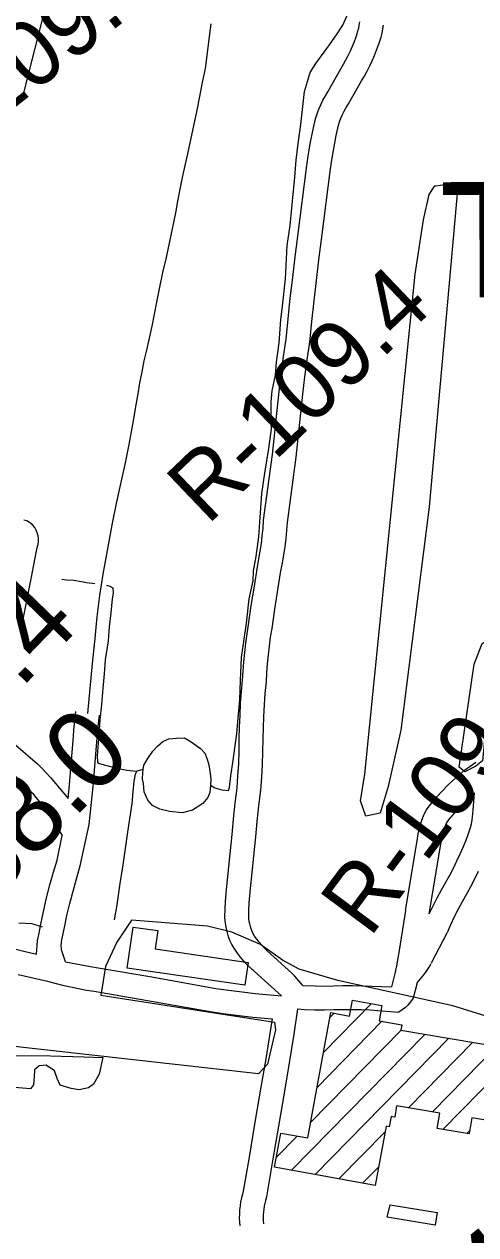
# Model space of a CAD drawing. Extents: x 3625074 to 3663148, y 511451 to 537151.
# Drawn here: x 3636401 to 3636969, y 521312 to 522833 of the extents above; entities that cross this region are included whole.
import ezdxf

# ---------------------------------------------------------------- set-up
doc = ezdxf.new("R2010")
doc.units = 0
for name, color, linetype in [('V-BLDG-OTLN', 7, 'Continuous'), ('V-RIVR-RANG-IDEN', 7, 'Continuous'), ('V-ROAD-CNTR', 7, 'Continuous'), ('V-SITE-OTLN', 7, 'Continuous'), ('V-SITE-VEGE', 7, 'Continuous'), ('V-SURV-IDEN', 7, 'Continuous'), ('V-TOPO-GNAM-IDEN', 7, 'Continuous'), ('V-TOPO-SHOR', 7, 'Continuous')]:
    doc.layers.add(name, color=color, linetype=linetype)

msp = doc.modelspace()

# ---------------------------------------------------------------- linework, layer by layer
at = {"layer": 'V-BLDG-OTLN'}
for p, q in [((3636777.2, 521541.2), (3636837.4, 521602.6)), ((3636769.2, 521497.4), (3636850.7, 521580.5)), ((3636785.2, 521585.1), (3636790.6, 521590.6)), ((3636737.3, 521393.4), (3636904.7, 521564.1)), ((3636761.2, 521453.5), (3636874.8, 521569.3)), ((3636767, 521388), (3636934.7, 521559.1)), ((3636884.2, 521471.8), (3636964.8, 521554)), ((3636914.2, 521466.7), (3636994.9, 521549)), ((3636927.5, 521444.6), (3636998, 521516.5)), ((3636796.8, 521382.6), (3636854.7, 521441.7)), ((3636957.6, 521439.6), (3636960.9, 521443)), ((3636718.2, 521409.6), (3636744.4, 521436.3)), ((3636826.5, 521377.2), (3636846.7, 521397.8))]:
    msp.add_line(p, q, dxfattribs=at)
for points in [[(3636538.1, 521698.9), (3636569, 521694.7), (3636565.6, 521671.7), (3636682.8, 521654.5), (3636678.6, 521625.7), (3636530.6, 521647.4)], [(3636857.3, 521334.4), (3636861.3, 521350.1), (3636920.3, 521340.1), (3636917.7, 521324.3)]]:
    msp.add_lwpolyline(points, close=True, dxfattribs=at)
msp.add_lwpolyline([(3636983.9, 521455.8), (3636963.7, 521459.2), (3636960.3, 521439.1), (3636920.2, 521445.8), (3636923.5, 521465.2), (3636869.2, 521474.3), (3636866.8, 521460.1), (3636862.3, 521461), (3636859.9, 521448), (3636856, 521448.8), (3636842.4, 521374.3), (3636715.9, 521397.3), (3636723.7, 521440.1), (3636757.7, 521433.9), (3636786.4, 521591.4), (3636810.1, 521587.1), (3636813.7, 521606.9), (3636850.7, 521600.2), (3636847.2, 521581.1), (3636875.9, 521576.2), (3636874.7, 521569.2), (3636998.5, 521548.4)], dxfattribs=at)
at = {"layer": 'V-ROAD-CNTR'}
msp.add_line((3636913.3, 521653.8), (3636932.7, 521691.6), dxfattribs=at)
for points in [[(3636398, 522737.1), (3636414.4, 522801.4), (3636427.4, 522852.1)], [(3636481, 521967.4), (3636484, 521998.8), (3636487.1, 522030.2), (3636490.5, 522061.6), (3636491.6, 522075.2), (3636492.9, 522088.7), (3636494.4, 522102.2), (3636496.1, 522115.6), (3636498.1, 522129), (3636500.3, 522142.4), (3636512.1, 522206.2), (3636517.2, 522230.9), (3636522.5, 522255.6), (3636528.1, 522280.2), (3636533.1, 522305.2), (3636537.7, 522330.2), (3636542, 522355.2), (3636544.2, 522369), (3636546.6, 522382.8), (3636549.3, 522396.5), (3636552.1, 522410.2), (3636555.2, 522423.8), (3636558.7, 522438.8), (3636562, 522453.8), (3636565, 522468.9), (3636567.7, 522484), (3636571.5, 522502.7), (3636575.5, 522521.4), (3636579.8, 522540), (3636591.6, 522596.1), (3636594.3, 522611), (3636597.1, 522626), (3636600.1, 522640.8), (3636603.4, 522655.7), (3636606.8, 522670.5), (3636618.5, 522725), (3636621.7, 522742.5), (3636625.1, 522760), (3636628.8, 522777.4), (3636635.5, 522827.4), (3636636.1, 522833.5)], [(3636724.4, 521612.4), (3636686, 521647.1), (3636681.5, 521651.4), (3636677.2, 521656), (3636673.2, 521660.9), (3636669.3, 521665.9), (3636665.7, 521671.1), (3636662, 521677), (3636659.7, 521682.1), (3636658, 521686.8), (3636656.5, 521691.6), (3636655.3, 521696.5), (3636654.4, 521701.4), (3636653.7, 521706.4), (3636653.4, 521711.6), (3636653.6, 521721.7), (3636654, 521731.4), (3636654.8, 521741), (3636655.8, 521750.4), (3636662.5, 521815.1), (3636664.2, 521834.6), (3636666.3, 521854.4), (3636668.7, 521873.7), (3636669.8, 521888.9), (3636670.7, 521904.3), (3636671.2, 521919.8), (3636671.5, 521935.4), (3636671.8, 521950.2), (3636672.4, 521965), (3636673.2, 521979.9), (3636674.3, 521994.7), (3636675.6, 522009.1), (3636676.3, 522020.4), (3636677.2, 522032.1), (3636678.4, 522043.8), (3636679.7, 522055.5), (3636681.2, 522067.1), (3636682.9, 522078.6), (3636686.6, 522102.8), (3636690.4, 522127.1), (3636694.3, 522151.6), (3636696.2, 522161.5), (3636697.8, 522171), (3636699.2, 522180.6), (3636700.4, 522190.2), (3636701.3, 522199.8), (3636702, 522210.1), (3636713.1, 522292.8), (3636721.6, 522371.8), (3636724.2, 522393.9), (3636727.1, 522415.9), (3636730.3, 522437.4), (3636732.8, 522463), (3636735.6, 522489), (3636738.6, 522514.9), (3636741.8, 522540.9), (3636745.2, 522566.7), (3636756.4, 522655.7), (3636758.6, 522670.3), (3636761.1, 522684.8), (3636763.9, 522699.2), (3636767.2, 522714.2), (3636769.3, 522720.6), (3636771.5, 522726.4), (3636774, 522732.1), (3636776.7, 522737.7), (3636779.7, 522743.2), (3636782.6, 522748.1), (3636799.3, 522777.2), (3636802.6, 522782.9), (3636805.6, 522788.4), (3636808.5, 522794), (3636811.2, 522799.7), (3636813.7, 522805.5), (3636816.1, 522811.3), (3636818.3, 522817.3), (3636819.6, 522821.2), (3636820.7, 522824.8), (3636821.6, 522828.4), (3636822.3, 522832.1), (3636822.9, 522836.2)], [(3636751.5, 521625.6), (3636741.4, 521637), (3636737.4, 521641), (3636706.6, 521668.9), (3636703, 521672.4), (3636699.7, 521676), (3636696.5, 521679.7), (3636693.6, 521683.5), (3636690.8, 521687.6), (3636688.6, 521691.1), (3636687.5, 521693.5), (3636686.4, 521696.6), (3636685.4, 521699.7), (3636684.6, 521702.8), (3636684, 521706), (3636683.6, 521709.3), (3636683.4, 521712.3), (3636683.6, 521720.7), (3636684, 521729.5), (3636684.7, 521738.2), (3636685.7, 521747.2), (3636692.4, 521812.2), (3636694.1, 521831.7), (3636696.2, 521851), (3636698.6, 521870.7), (3636699.8, 521887), (3636700.7, 521903), (3636701.2, 521919), (3636701.5, 521934.8), (3636701.8, 521949.3), (3636702.4, 521963.6), (3636703.2, 521977.9), (3636704.2, 521992.2), (3636705.6, 522006.8), (3636706.2, 522018.4), (3636707.1, 522029.5), (3636708.2, 522040.7), (3636709.5, 522051.8), (3636710.9, 522062.9), (3636712.6, 522074.1), (3636716.3, 522098.3), (3636720, 522122.4), (3636723.9, 522146.3), (3636725.8, 522156.2), (3636727.5, 522166.4), (3636729, 522176.7), (3636730.2, 522187), (3636731.2, 522197.3), (3636731.9, 522207), (3636742.8, 522289.2), (3636751.4, 522368.5), (3636754, 522390.2), (3636756.8, 522411.7), (3636760, 522433.7), (3636762.6, 522459.9), (3636765.4, 522485.6), (3636768.4, 522511.4), (3636771.6, 522537), (3636775, 522562.8), (3636786.1, 522651.6), (3636788.3, 522665.5), (3636790.7, 522679.3), (3636793.3, 522693.2), (3636796.2, 522706.3), (3636797.6, 522710.4), (3636799.3, 522715.1), (3636801.3, 522719.6), (3636803.4, 522724), (3636805.8, 522728.4), (3636808.6, 522733), (3636825.2, 522762.2), (3636828.7, 522768.1), (3636832.1, 522774.4), (3636835.4, 522780.8), (3636838.5, 522787.3), (3636841.4, 522793.8), (3636844.1, 522800.5), (3636846.5, 522807.1), (3636848.2, 522811.8), (3636849.7, 522816.9), (3636851, 522822.1), (3636851.9, 522827.3), (3636852.6, 522832.2)], [(3636400.2, 522087.9), (3636410.4, 522138.4), (3636412.7, 522151.8), (3636415.2, 522164.7), (3636418, 522177.4), (3636418.6, 522179.6), (3636419.1, 522183.3), (3636419, 522186.9), (3636418.6, 522190.6), (3636417.6, 522194.1), (3636416.2, 522197.5), (3636414.3, 522200.7), (3636411.5, 522204.4), (3636407.8, 522207.2), (3636404.3, 522209.1), (3636400.6, 522210.3)], [(3636452.9, 521655.1), (3636448.5, 521668.9), (3636448.1, 521670.8), (3636447.8, 521672.6), (3636447.6, 521674.5), (3636447.6, 521676.4), (3636447.8, 521678.4), (3636448, 521680.2), (3636448.6, 521682.9), (3636451.7, 521698.4), (3636454.9, 521713.5), (3636458.3, 521728.5), (3636462.5, 521743.9), (3636466.8, 521759.4), (3636471.6, 521775.6), (3636478.5, 521808.5), (3636482.6, 521827.8), (3636484.6, 521843.8), (3636486.3, 521859.4), (3636487.8, 521874.9), (3636493, 521936.5), (3636493.4, 521944), (3636494, 521951), (3636494.8, 521958), (3636495.9, 521965.2)], [(3636456.2, 521860.2), (3636457.9, 521877.6), (3636463.1, 521938.6), (3636463.5, 521946.1), (3636464.2, 521954), (3636465.1, 521961.9), (3636466.2, 521969.6)], [(3636367.2, 521944), (3636382.8, 521933.1), (3636390.7, 521927.3), (3636417.7, 521904), (3636423.5, 521898.3), (3636428.9, 521892.5), (3636434.2, 521886.6), (3636456.2, 521860.2)], [(3636345.3, 521922.7), (3636365.3, 521908.7), (3636371.9, 521903.8), (3636397.3, 521882), (3636402, 521877.3), (3636406.8, 521872.2), (3636411.4, 521867), (3636415.9, 521861.7), (3636420.3, 521856.1), (3636425.4, 521849.3), (3636430.4, 521842.5), (3636435.1, 521835.6), (3636449, 521814)], [(3636880.5, 521719.7), (3636894.7, 521804.7), (3636895.4, 521810), (3636896.4, 521815.9), (3636897.7, 521821.7), (3636899.3, 521827.4), (3636901.1, 521833.1), (3636903.2, 521838.6), (3636906.2, 521845.6), (3636913.4, 521854.8), (3636919.9, 521862.4), (3636926.6, 521869.8), (3636933.2, 521876.6), (3636939.9, 521883.1), (3636946.9, 521889.5), (3636954.4, 521896), (3636968.8, 521906.2)], [(3636910.2, 521715.3), (3636920.4, 521735.5), (3636925.8, 521745.6), (3636931.3, 521755.4), (3636936.1, 521764.2), (3636940.7, 521773), (3636945, 521781.9), (3636949.2, 521790.9), (3636953.2, 521799.9), (3636957, 521809.2), (3636958.9, 521814.1), (3636960.6, 521818.9), (3636962, 521823.8), (3636963.3, 521828.7), (3636964.2, 521833.2), (3636965.4, 521845.6), (3636967.1, 521867.7)], [(3636910.2, 521715.3), (3636924.4, 521800.4), (3636925.1, 521805.5), (3636925.8, 521810), (3636926.8, 521814.5), (3636928, 521818.9), (3636929.4, 521823.2), (3636931, 521827.5), (3636932.2, 521830.1), (3636936.6, 521835.8), (3636942.4, 521842.6), (3636948.5, 521849.2), (3636954.4, 521855.4), (3636967.1, 521867.7)], [(3636416.7, 521664.7), (3636417.9, 521681.6), (3636418.5, 521685.8), (3636419.3, 521689.1), (3636422.3, 521704.4), (3636425.6, 521720), (3636429.2, 521735.7), (3636433.5, 521751.8), (3636438, 521767.7), (3636442.5, 521782.9), (3636449, 521814)], [(3636120.5, 521776), (3636182, 521745.2), (3636243.7, 521713.8), (3636254.7, 521708.9), (3636266, 521704.2), (3636277.1, 521699.9), (3636288, 521696.7), (3636299.3, 521693.5), (3636310.7, 521690.5), (3636322.2, 521687.7), (3636334, 521685.1), (3636382.4, 521673.1), (3636400.6, 521668.6), (3636416.7, 521664.7)], [(3636933, 521692.2), (3636937.5, 521702.2), (3636942.1, 521712), (3636947, 521721.6), (3636952.1, 521731.2), (3636957.5, 521740.8), (3636962.6, 521750), (3636967.5, 521759.4), (3636972.1, 521768.9)], [(3636880.5, 521719.6), (3636872.4, 521669.4), (3636870.8, 521659.7), (3636869, 521650.1), (3636866.9, 521640.7), (3636862.9, 521623.8)], [(3636452.9, 521655.1), (3636484.4, 521649.4), (3636494.1, 521647.8), (3636561.5, 521636.2), (3636642, 521621.8), (3636658.4, 521619.5), (3636674.9, 521617.4), (3636691.4, 521615.6), (3636724.4, 521612.4)], [(3636393.5, 521639.4), (3636412, 521635), (3636430.2, 521630.9), (3636439.6, 521628.4), (3636449.4, 521625.9), (3636459.3, 521623.7), (3636469.3, 521621.6), (3636479.3, 521619.8), (3636489.1, 521618.2), (3636556.3, 521606.6), (3636637.3, 521592.2), (3636654.3, 521589.8), (3636671.3, 521587.6), (3636688.3, 521585.7), (3636712.7, 521583.4)], [(3636895.1, 521629), (3636903.4, 521638.9), (3636906.9, 521643.5), (3636910.1, 521648.3), (3636912.8, 521652.9)], [(3636751.5, 521625.6), (3636766.9, 521625), (3636778.4, 521624.8), (3636789.8, 521625.2), (3636801.7, 521625.3), (3636813.6, 521625.3), (3636825.4, 521625.1), (3636862.9, 521623.8)], [(3636895.1, 521629), (3636890, 521609.5)], [(3636890, 521609.5), (3636885.5, 521603.2), (3636883, 521600.4), (3636880.3, 521597.9), (3636872.2, 521592.1)], [(3636744.8, 521596.1), (3636740, 521564.2), (3636734.3, 521528.4), (3636728.3, 521492.7), (3636720.8, 521448.8), (3636713.3, 521405), (3636705.8, 521360.1), (3636704.4, 521355.4), (3636703.5, 521351.8), (3636702.7, 521348.2), (3636702.2, 521344.6), (3636701.8, 521341), (3636701.6, 521337.3), (3636701.5, 521333.7), (3636701.7, 521330), (3636702, 521326)], [(3636744.8, 521596.1), (3636753.6, 521595.5), (3636766, 521595), (3636778.7, 521594.8), (3636790.5, 521595.2), (3636801.9, 521595.3), (3636813.2, 521595.3), (3636824.6, 521595.1), (3636835.9, 521594.7), (3636845.8, 521594.1), (3636872.2, 521592.1)], [(3636712.7, 521583.4), (3636704.7, 521533.3), (3636698.7, 521497.7), (3636691.2, 521453.8), (3636683.7, 521409.9), (3636676.5, 521367), (3636675.5, 521363.4), (3636674.2, 521358.5), (3636673.2, 521353.5), (3636672.4, 521348.5), (3636671.9, 521343.5), (3636671.6, 521338.4), (3636671.5, 521333.3), (3636671.7, 521328.3), (3636672.1, 521323.5)]]:
    msp.add_lwpolyline(points, dxfattribs=at)
at = {"layer": 'V-SITE-OTLN'}
msp.add_lwpolyline([(3637141, 521537.4), (3636939.8, 521600.1), (3636795.3, 521631.8), (3636746.8, 521646.1), (3636726, 521657.4), (3636698.3, 521677), (3636662.3, 521692.6), (3636631.7, 521699.8), (3636535.8, 521707.5), (3636517.5, 521679.8), (3636503.3, 521649.3), (3636497.5, 521613.2), (3636715.7, 521579.5), (3636717, 521569.8), (3636706.9, 521526.7), (3636695.7, 521514.3), (3636377.4, 521550.1)], dxfattribs=at)
at = {"layer": 'V-SITE-VEGE'}
for points in [[(3636946.5, 522634.3), (3636910, 522227), (3636874.5, 521946.2), (3636858.6, 521875.4), (3636848.6, 521842.1), (3636830.5, 521838.1), (3636823.7, 521857.6), (3636829.5, 521890.9), (3636892.7, 522519.2), (3636903, 522587.3), (3636910.2, 522619.3), (3636917.2, 522630.3), (3636918.6, 522630.3)], [(3636947.8, 521899.8), (3636966.9, 522029), (3636976.8, 522055.3), (3636986.6, 522060.8), (3636990.7, 522051.1), (3636990.7, 522045.5), (3636977.1, 521907.9), (3636968.7, 521901), (3636954.8, 521894.1)]]:
    msp.add_lwpolyline(points, close=True, dxfattribs=at)
msp.add_lwpolyline([(3636389.8, 521537.6), (3636434.1, 521537.2), (3636476.1, 521535.8), (3636499.8, 521534.8), (3636495.5, 521514.2), (3636488.1, 521501.3), (3636482, 521496.8), (3636470.1, 521494.2), (3636460.2, 521496.2), (3636446.5, 521500.1), (3636442.7, 521508.5), (3636439.3, 521518.1), (3636428.7, 521525.4), (3636419.9, 521524.4), (3636414.1, 521519.4), (3636414.1, 521517.5), (3636412.8, 521500.7), (3636409, 521495.8), (3636383.8, 521497.9)], dxfattribs=at)
at = {"layer": 'V-TOPO-SHOR'}
for points in [[(3636635.1, 521877.3), (3636640.8, 521874), (3636649.6, 521871.2), (3636657.9, 521870.3), (3636659.2, 521874.3), (3636660.9, 521888.8), (3636663.6, 521908.3), (3636668.4, 521942.1), (3636670.8, 521970.8), (3636672.1, 521984.5), (3636673.1, 522008.6), (3636674.3, 522037.7), (3636680.6, 522080.7), (3636683.7, 522111.3), (3636688.8, 522133.8), (3636689.5, 522146.5), (3636692.6, 522164.6), (3636696, 522189.1), (3636697.1, 522207.4), (3636700, 522243.4), (3636703.4, 522269.3), (3636708.6, 522300.3), (3636711.8, 522324.8), (3636711.4, 522358.7), (3636712.7, 522372.6), (3636717.1, 522392.3), (3636718.2, 522408.6), (3636721.4, 522432.9), (3636723.6, 522461.7), (3636725.7, 522478.8), (3636729.5, 522513.1), (3636731.7, 522555.1), (3636735.4, 522580.1), (3636737.4, 522602), (3636739.3, 522619.7), (3636740.8, 522636.1), (3636742.8, 522662.3), (3636745.2, 522679.8), (3636748.7, 522707.1), (3636753.6, 522748.5), (3636757.1, 522761.4), (3636760.6, 522772.7), (3636767.9, 522784), (3636778.3, 522798.1), (3636784.8, 522807.4), (3636794.6, 522821.1), (3636801.5, 522832.2), (3636811.6, 522854.6)], [(3636448.6, 522135.9), (3636454.4, 522135.1), (3636463.4, 522134.6), (3636473.1, 522133.1), (3636479.3, 522131.9), (3636489.8, 522130.6)], [(3636504.5, 522128.5), (3636508.7, 522127.1), (3636512.7, 522125.2), (3636512.8, 522118.5), (3636511.6, 522111.3), (3636509.9, 522093.8), (3636508.1, 522075.9), (3636506.6, 522058.6), (3636502.8, 522034.7), (3636501.7, 522017), (3636499.8, 521998.7), (3636498.4, 521978.4), (3636496.3, 521959.3), (3636495, 521940.8), (3636493, 521913.9), (3636493.1, 521905.9), (3636494.1, 521904.7), (3636498.8, 521903.5), (3636515.7, 521899), (3636530.1, 521895.9), (3636542.5, 521894.7)], [(3636551.3, 521902.3), (3636556.4, 521910.5), (3636563, 521920), (3636568.6, 521926.3), (3636575.2, 521932), (3636583, 521935.2), (3636592.5, 521936.4), (3636602.8, 521936.6), (3636611.1, 521931.8), (3636622.6, 521923.1), (3636628.3, 521917.5), (3636631.3, 521910), (3636633, 521902.9), (3636634.7, 521891.9), (3636635.6, 521884.1), (3636635.1, 521877.3), (3636634.5, 521868), (3636632, 521861.5), (3636625.6, 521854), (3636612.7, 521845.8), (3636599.9, 521842.6), (3636583.6, 521844), (3636571.5, 521847.1), (3636562.2, 521851.4), (3636556.5, 521858.3), (3636552.1, 521868.6), (3636550.9, 521879.4), (3636549.7, 521884.7), (3636550.2, 521893), (3636550.5, 521897), (3636551.3, 521902.3)], [(3636550.5, 521897), (3636547.1, 521896), (3636542.5, 521894.7), (3636540.5, 521890.9), (3636539.1, 521882.2), (3636537.6, 521868.8), (3636536.2, 521854.3), (3636534.2, 521840.2), (3636530.8, 521818.3), (3636528.1, 521797.6), (3636524.9, 521777.1), (3636521.3, 521753.6), (3636517.4, 521726.6), (3636514.2, 521708.1)], [(3636394.2, 521704.3), (3636410.5, 521703.2), (3636423.8, 521699.3)]]:
    msp.add_lwpolyline(points, dxfattribs=at)

# ---------------------------------------------------------------- texts
at = {"layer": 'V-RIVR-RANG-IDEN'}
for s, rotation, p in [('R-109.5', 38.2251, (3636270.4, 522634.6)), ('R-109.4', 43.6733, (3636631.2, 522202.7)), ('R-109.2', 53.3739, (3636835.5, 521684.1))]:
    msp.add_text(s, height=83, rotation=rotation, dxfattribs=at).set_placement(p)
at = {"layer": 'V-SURV-IDEN'}
for s, rotation, p in [('309+66.4', 45.9555, (3636083.3, 521673.6)), ('310+88.0', 45.9079, (3636149.5, 521510.6)), ('319+48.5', 38.9187, (3636755.7, 521017.2))]:
    msp.add_text(s, height=100, rotation=rotation, dxfattribs=at).set_placement(p)
at = {"layer": 'V-TOPO-GNAM-IDEN'}
msp.add_text('TWELVE', height=145, rotation=0.1955, dxfattribs=at).set_placement((3636923.5, 522489.7))

doc.saveas('drawing.dxf')
